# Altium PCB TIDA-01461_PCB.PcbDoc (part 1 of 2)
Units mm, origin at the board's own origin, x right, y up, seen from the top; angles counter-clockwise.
Board outline 92.5 x 57.5 mm, 4 copper layers (Top Layer, Mid Layer 1, Mid Layer 2, Bottom Layer), stack 1.54 mm thick; 150 components, 62 nets, 436 pads, 169 vias.
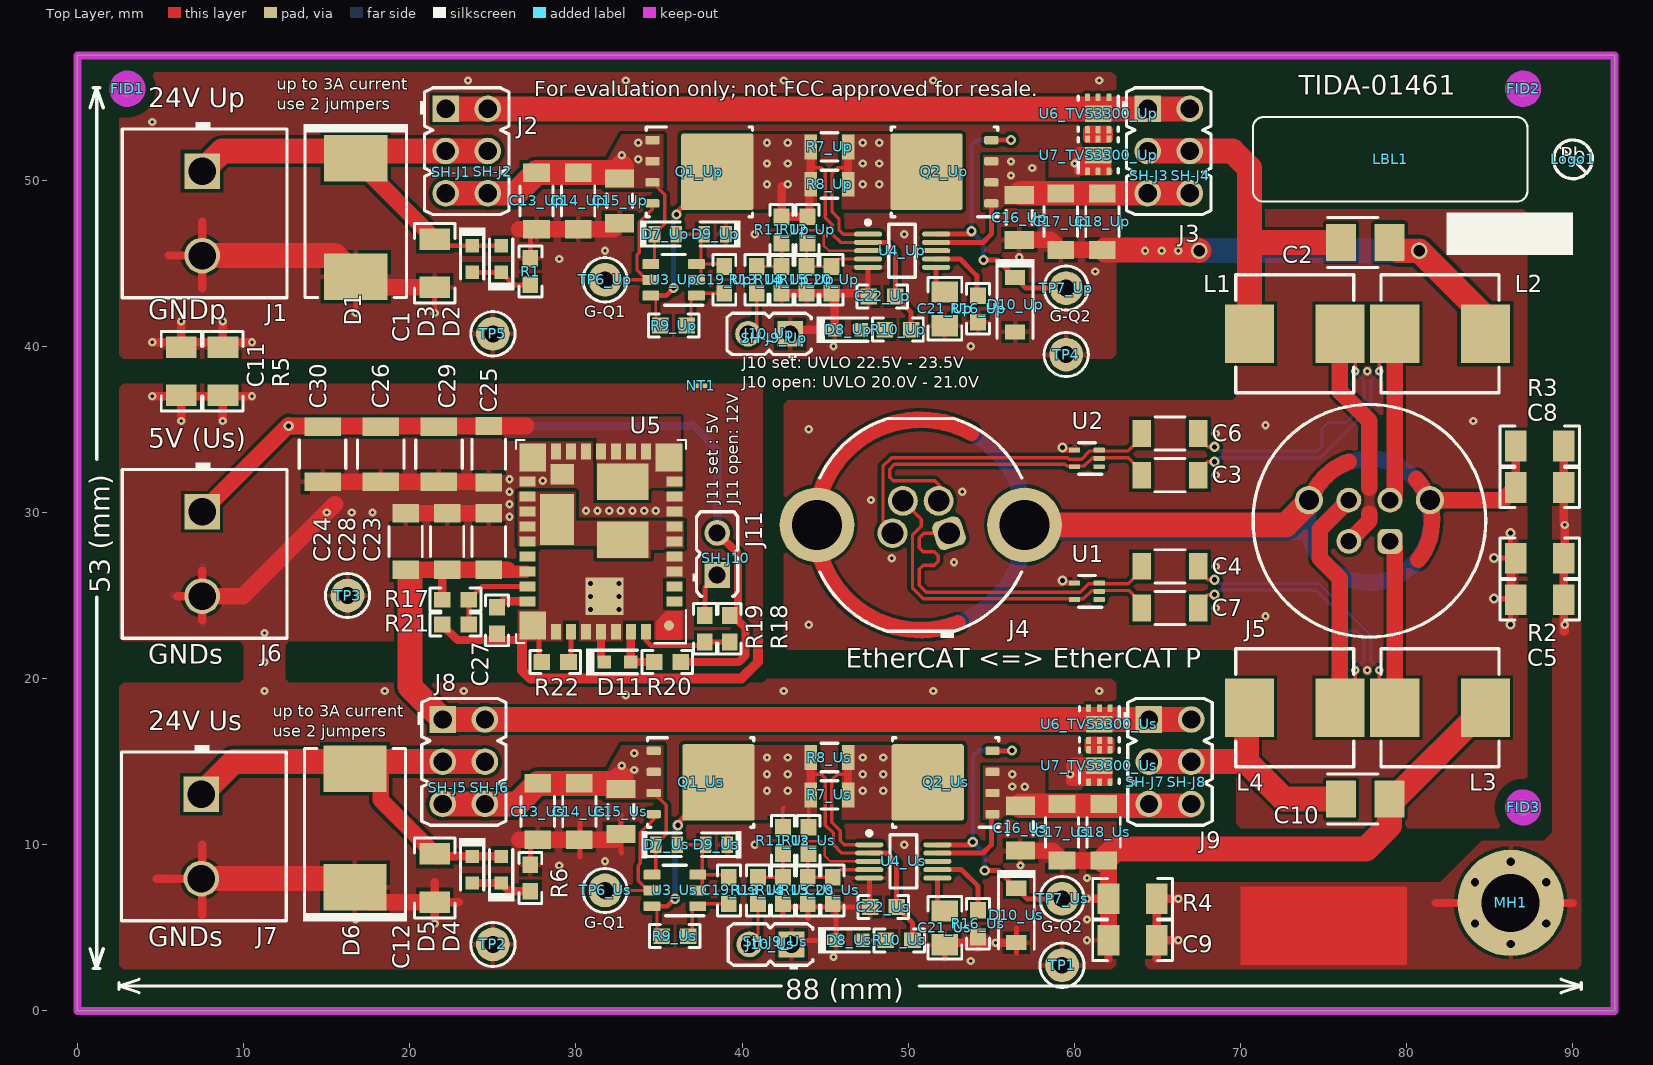
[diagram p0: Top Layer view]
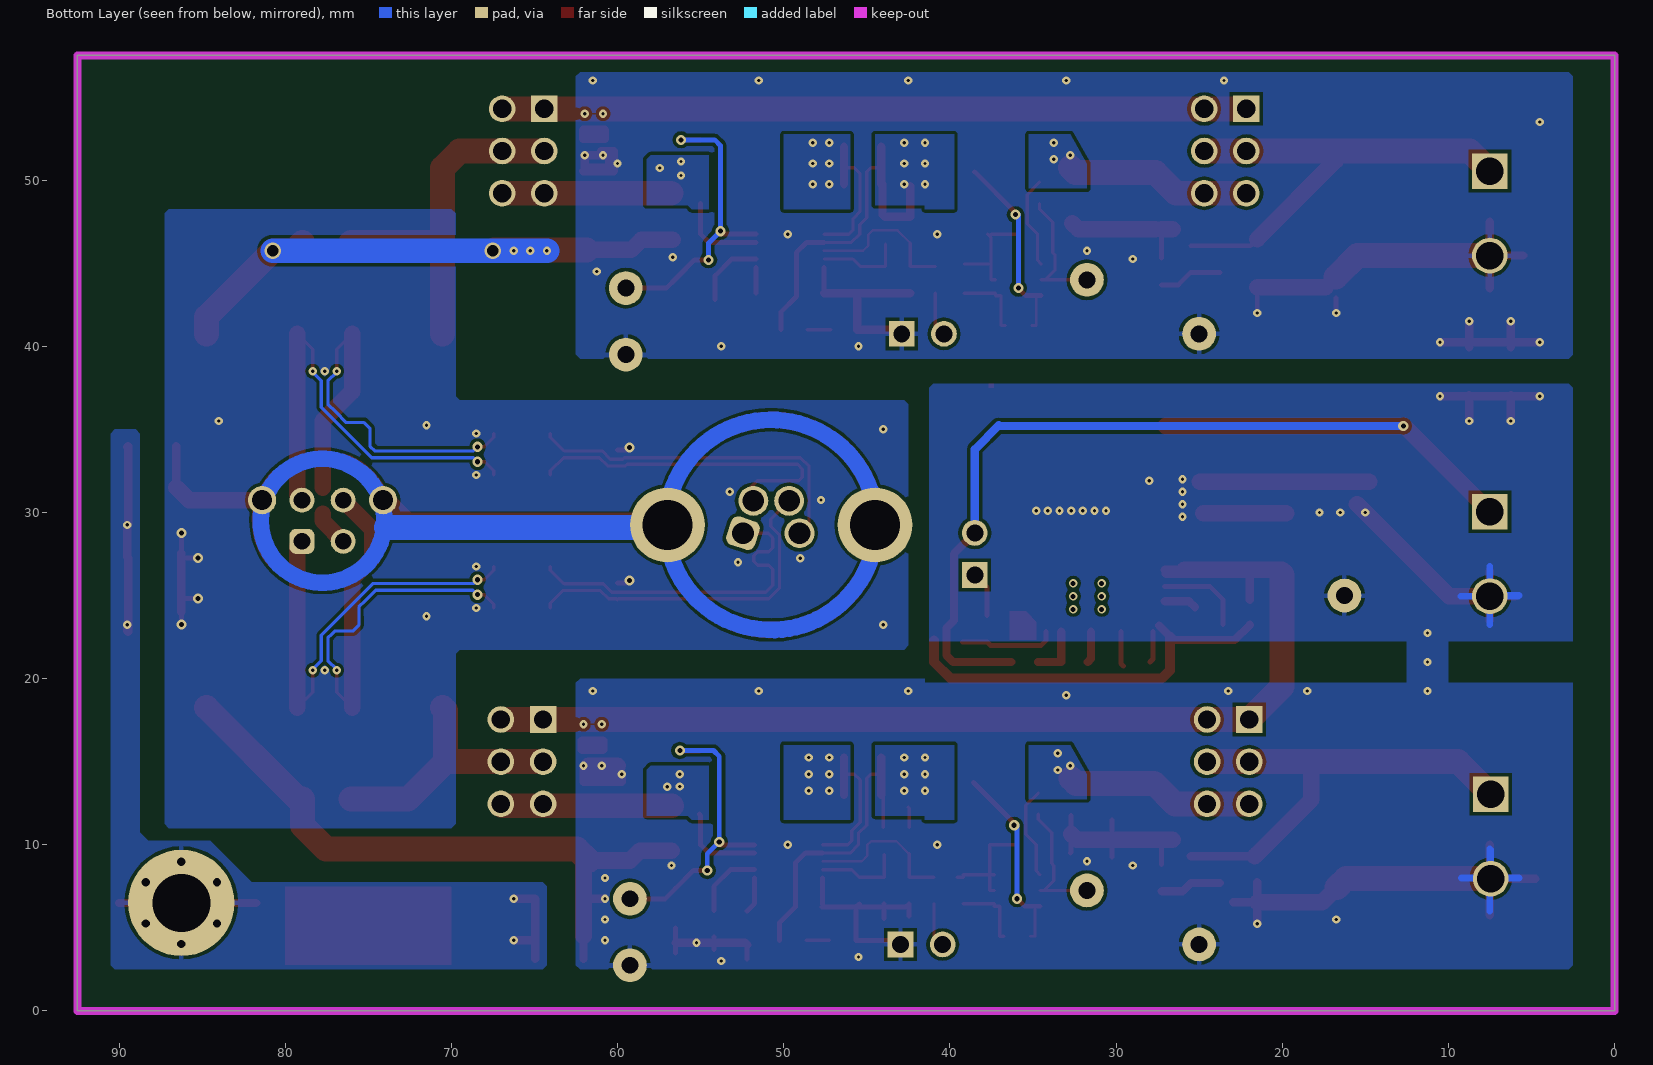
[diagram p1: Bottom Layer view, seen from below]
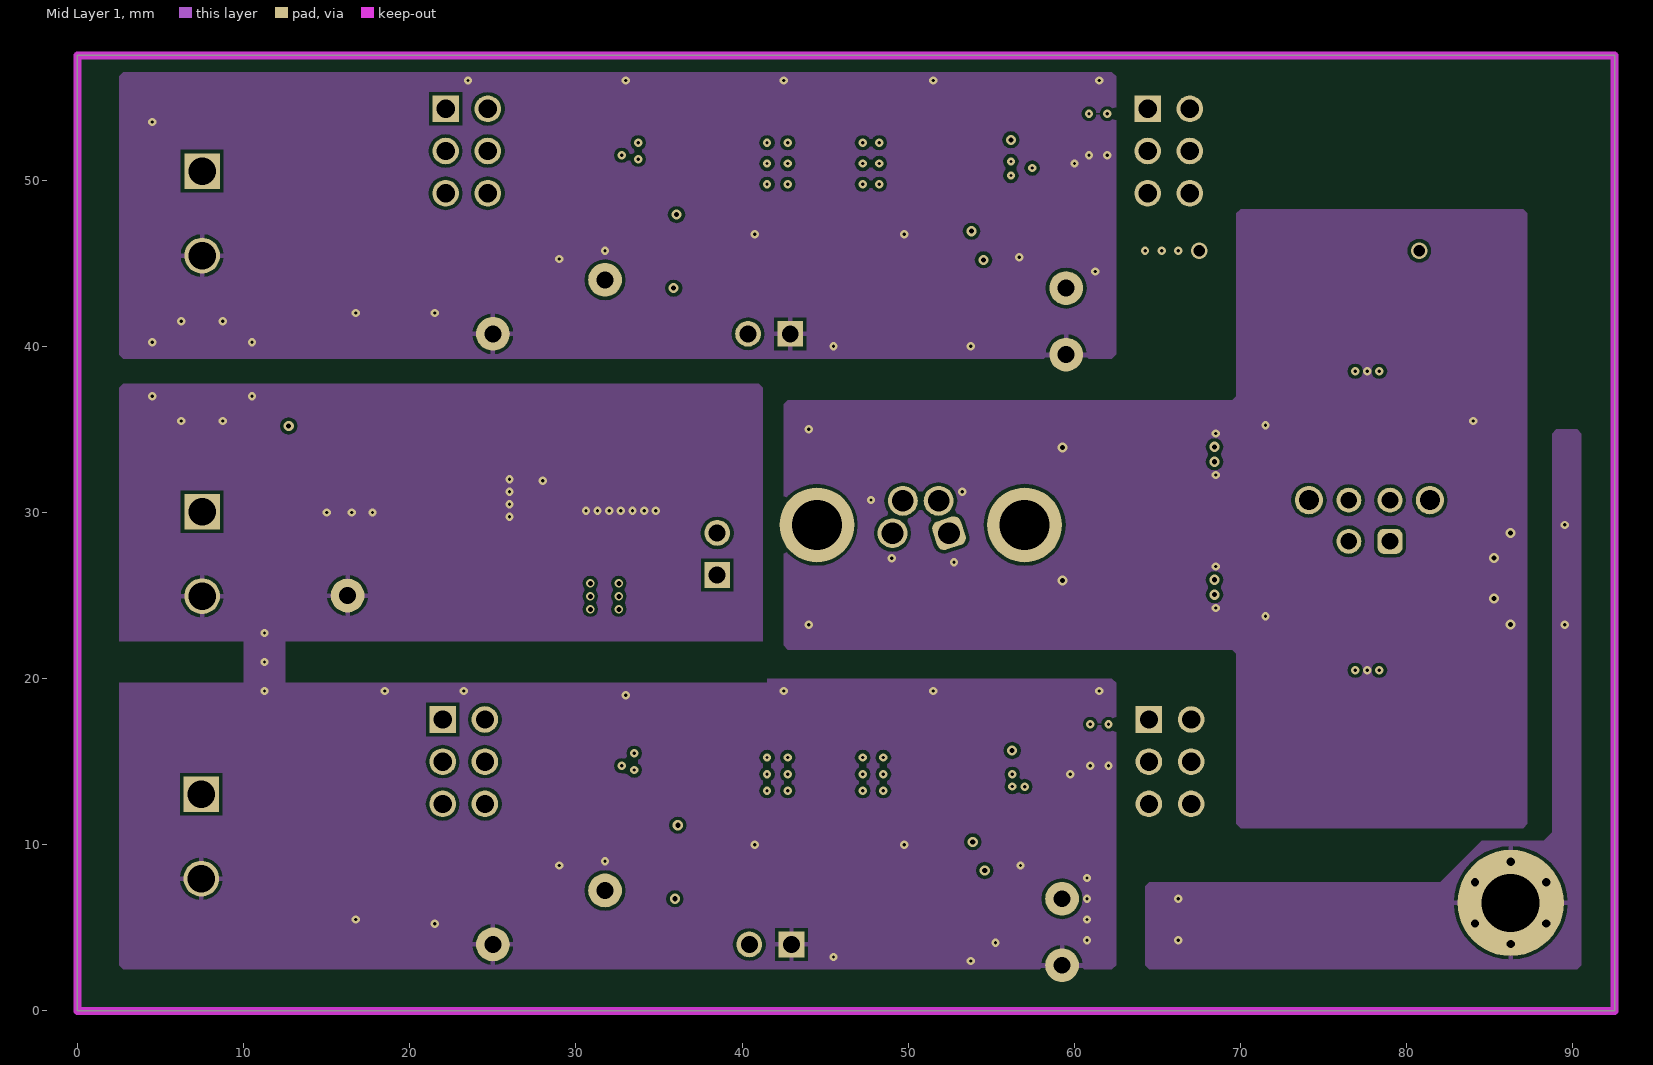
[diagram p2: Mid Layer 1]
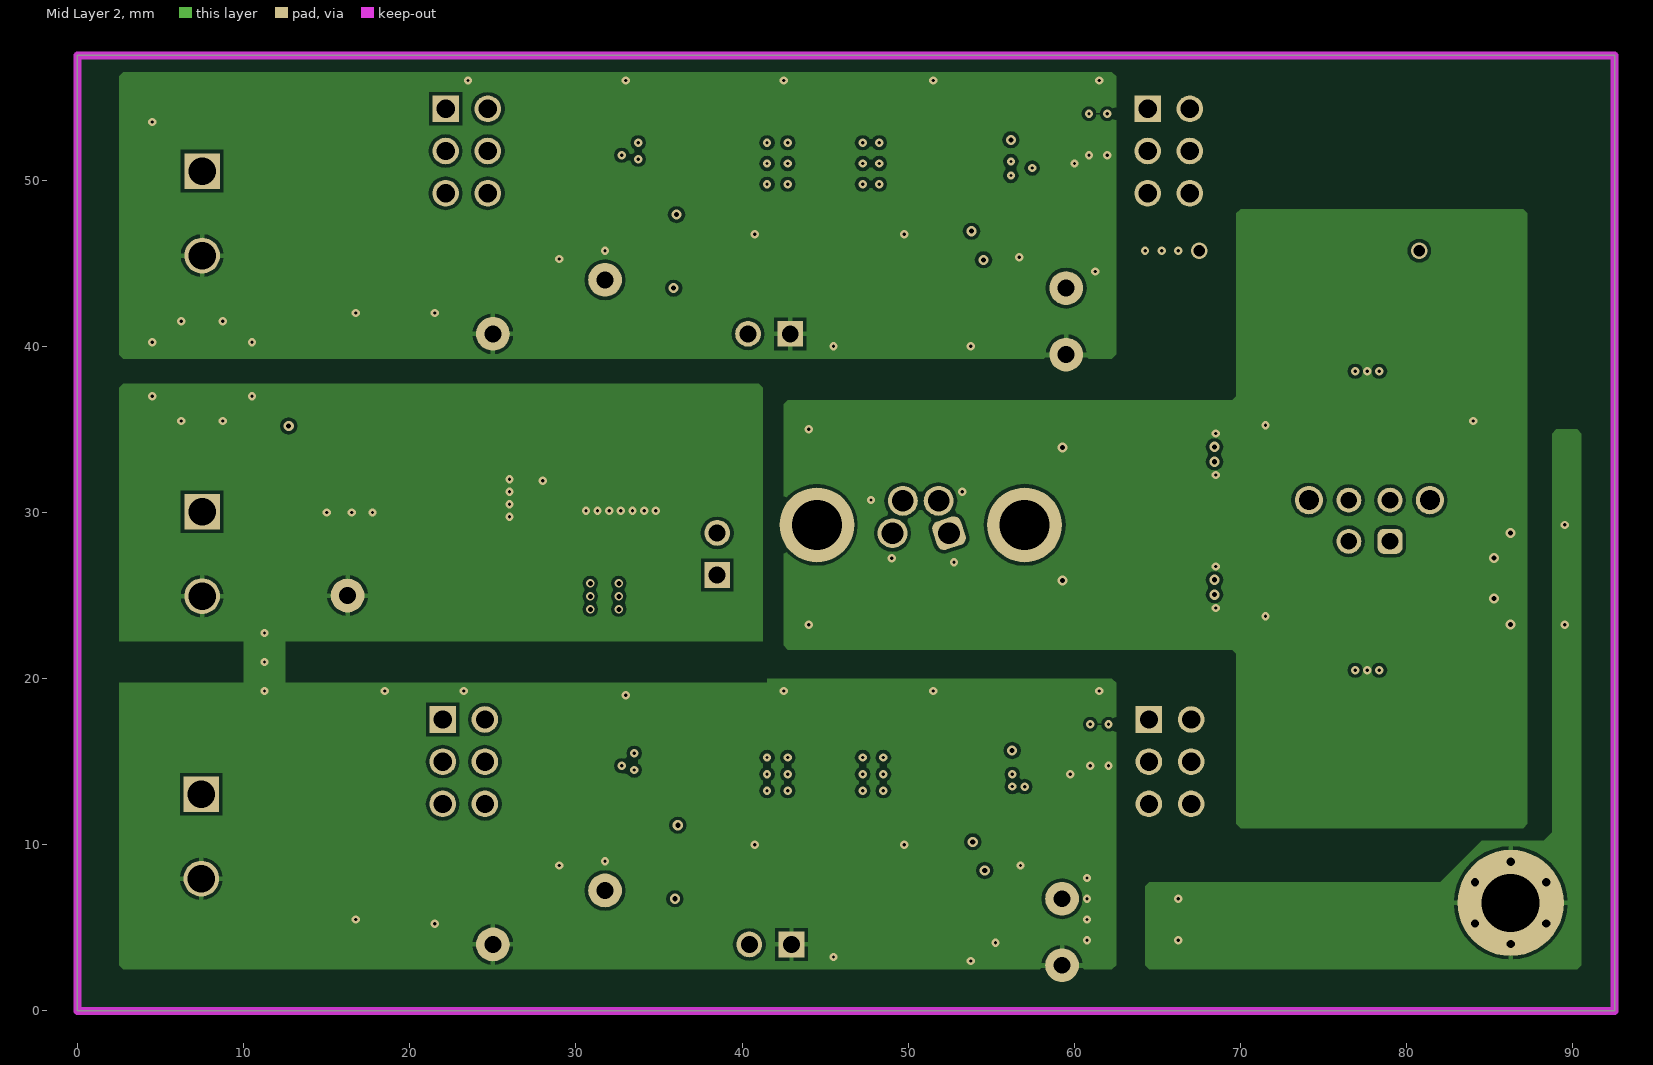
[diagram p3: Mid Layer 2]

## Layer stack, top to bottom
Top Solder: solder mask 0.015, Solder Resist, Dk 3.3
Top Layer: signal copper 0.035
Dielectric1: prepreg 0.2, FR-4, Dk 4.3
Mid Layer 1: signal copper 0.035
Dielectric 2: core 1, FR-4, Dk 4.6
Mid Layer 2: signal copper 0.035
Dielectric 3: prepreg 0.2, FR-4, Dk 4.3
Bottom Layer: signal copper 0.035
Bottom Solder: solder mask 0.015, Solder Resist, Dk 3.3

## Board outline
0,0 0,57.5 92.5,57.5 92.5,0

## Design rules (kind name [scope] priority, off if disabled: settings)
AcuteAngle [All] p1: minimum=4.50000000000000E+0001 checktracksonly=FALSE
AssemblyTestPointUsage [All] p1: valid=2
Clearance Clearance_FID [IsKeepOut and InComponentClass('FiducialMark') vs IsPad and InComponentClass('FiducialMark')] p1: gap=0 ignorepadtopadclearanceinfootprint=FALSE
Clearance Clearance_NetTie [InComponent('NT1')] p2: gap=0 ignorepadtopadclearanceinfootprint=TRUE
Clearance Clearance_PolysAGND-GND [InNamedPolygon('TOP_LAYER_GND_P243') vs InNamedPolygon('TOP_LAYER_AGND_P244')] p3: gap=0 ignorepadtopadclearanceinfootprint=FALSE
Clearance Clearance_MH [InComponent('MH1')] p4: gap=0.2 ignorepadtopadclearanceinfootprint=FALSE except(0: THPad-Via THPad-Hole)
Clearance Clearance_Keepouts [((IsTrack Or IsArc) And Not InPoly) And IsFree and IsKeepOut vs ((IsTrack Or IsArc) And Not InPoly) And IsFree and IsKeepOut] p5: gap=0 ignorepadtopadclearanceinfootprint=FALSE
Clearance Clearance_BoardEdge_MountingHoles [OnCopper and InComponentClass('Mounting Holes') vs IsKeepOut] p6: gap=1.016 ignorepadtopadclearanceinfootprint=FALSE except(0: Arc-Hole Track-Hole SMDPad-Hole THPad-Hole Via-Hole Fill-Hole Poly-Hole Region-Hole Text-Hole)
Clearance Clearance_BoardEdge_Poly [OnCopper and InPoly vs IsKeepOut] p7: gap=0.635 ignorepadtopadclearanceinfootprint=FALSE except(0: Arc-Hole Track-Hole SMDPad-Hole THPad-Hole Via-Hole Fill-Hole Poly-Hole Region-Hole Text-Hole)
Clearance Clearance_BoardEdge [OnCopper and Not InComponentClass('Logo') and not InComponentClass('FiducialMark') and not InRegion(1000,500,4000,800) and Not IsKeepout vs IsKeepOut] p8: gap=0.635 ignorepadtopadclearanceinfootprint=FALSE except(0: Arc-Hole Track-Hole SMDPad-Hole THPad-Hole Via-Hole Fill-Hole Poly-Hole Region-Hole Text-Hole)
Clearance Clearance_Poly [InPolygon] p9: gap=0.2 ignorepadtopadclearanceinfootprint=FALSE except(0: Arc-Hole Track-Hole SMDPad-Hole THPad-Hole Via-Hole Fill-Hole Poly-Hole Region-Hole Text-Hole)
Clearance [All] p10: gap=0.2 ignorepadtopadclearanceinfootprint=FALSE
ComponentClearance ComponentClearance_THtoTH_1 [HasFootprint('Major_BBB_SSHQ-123-D-08') vs HasFootprint('MTGP_4-40_PanHead')] p1: gap=0 collisioncheckmode=3 verticalgap=0 showdistances=FALSE
ComponentClearance ComponentClearance_MountingHoles_FiducialMarks [InComponentClass('Mounting Holes') vs InComponentClass('FiducialMark')] p2: gap=1.27 collisioncheckmode=3 verticalgap=0.254 showdistances=FALSE
ComponentClearance ComponentClearance_Shunt [InComponentClass('Header') vs InComponentClass('Shunt')] p3: gap=0 collisioncheckmode=3 verticalgap=0 showdistances=FALSE
ComponentClearance ComponentClearance_Logo [InComponentClass('Logo')] p4: gap=1.27 collisioncheckmode=3 verticalgap=0.254 showdistances=FALSE
ComponentClearance ComponentClearance_ScrewToNut [(HasFootprint('NY PMS 440 0025 PH')) vs (HasFootprint('Keystone_1902C'))] p5: gap=0.127 collisioncheckmode=3 verticalgap=0.254 showdistances=FALSE
ComponentClearance ComponentClearance_MountingHoles [InComponentClass('Mounting Holes')] p6: gap=6.35 collisioncheckmode=3 verticalgap=2540 showdistances=FALSE
ComponentClearance ComponentClearance_SmallPassives [HasFootprint('0201*') or HasFootprint('0402*') or HasFootprint('0508') or HasFootprint('0603*') or HasFootprint('0612') or HasFootprint('0805*') or HasFootprint('0815*') or HasFootprint('0830*') or HasFootprint('1206*') or HasFootprint('1210*') or HasFootprint('1808*') or HasFootprint('1812*') or HasFootprint('1825*') or HasFootprint('2010*') or HasFootprint('2220*') or HasFootprint('2225*') or HasFootprint('2512*') or HasFootprint('2728*') or HasFootprint('3518*') vs HasFootprint('0201*') or HasFootprint('0402*') or HasFootprint('0508') or HasFootprint('0603*') or HasFootprint('0612') or HasFootprint('0805*') or HasFootprint('0815*') or HasFootprint('0830*') or HasFootprint('1206*') or HasFootprint('1210*') or HasFootprint('1808*') or HasFootprint('1812*') or HasFootprint('1825*') or HasFootprint('2010*') or HasFootprint('2220*') or HasFootprint('2225*') or HasFootprint('2512*') or HasFootprint('2728*') or HasFootprint('3518*')] p7: gap=0.508 collisioncheckmode=3 verticalgap=0.254 showdistances=FALSE
ComponentClearance ComponentClearance_THtoSMT [IsThruComponent vs IsSMTComponent] p8: gap=0.508 collisioncheckmode=3 verticalgap=0.762 showdistances=FALSE
ComponentClearance ComponentClearance_THtoTH [IsThruComponent vs IsThruComponent] p9: gap=1.27 collisioncheckmode=3 verticalgap=0.508 showdistances=FALSE
DiffPairsRouting [All] p1: maxlimit=2 minlimit=0.2 mostfreqgap=0.2 toplayer_minwidth=0.2 toplayer_maxwidth=1 toplayer_prefwidth=0.2 midlayer1_minwidth=0.2 midlayer1_maxwidth=1 midlayer1_prefwidth=0.2 midlayer2_minwidth=0.2 midlayer2_maxwidth=1 midlayer2_prefwidth=0.2 bottomlayer_minwidth=0.2 bottomlayer_maxwidth=1 bottomlayer_prefwidth=0.2 maxuncoupledlength=25.4
FabricationTestPointUsage TestPointUsage [All] p1: valid=2 allowmultiple=FALSE
FabricationTestpoint Testpoint [All] p1: side=3 testpointundercomponent=TRUE minsize=1.016 maxsize=2.54 preferedsize=1.524 minholesize=0 maxholesize=1.016 preferedholesize=0.813 testpointgrid=0.025 allowsidetop=TRUE allowsidebottom=TRUE usegrid=TRUE gridtolerance=0
FanoutControl Fanout_LCC [IsLCC] p1: bgadir=Out bgaviamode=Centered fanoutstyle=Auto fanoutdirection=Alternating viagrid=0.025 // Fanout_LCC (Default Rule)
FanoutControl Fanout_BGA [IsBGA] p2: bgadir=Out bgaviamode=Centered fanoutstyle=Auto fanoutdirection=Alternating viagrid=0.025 // Fanout_BGA (Default Rule)
FanoutControl Fanout_Default [All] p4: bgadir=Out bgaviamode=Centered fanoutstyle=Auto fanoutdirection=Alternating viagrid=0.025 // Fanout_Default (Default Rule)
FanoutControl Fanout_Small [(CompPinCount < 5)] p5: bgadir=Out bgaviamode=Centered fanoutstyle=Auto fanoutdirection=OutThenIn viagrid=0.025 // Fanout_Small (Default Rule)
Height [All] p1: minheight=0 maxheight=26 prefheight=12.7
HoleSize [All] p1: absolutevalues=TRUE maxlimit=6.375 minlimit=0.2 maxpercent=80.000 minpercent=20.000
HoleToHoleClearance [All] p1: gap=0.2 allowstackedmicrovias=TRUE
MinimumAnnularRing MinimumAnnularRing_LMZ [InComponent('U5')] p1: minimumring=0.1
MinimumAnnularRing MinimumAnnularRing_ThermalPadVias [IsVia and InAnyComponent] p2: minimumring=0.15
MinimumAnnularRing [All] p3: minimumring=0.15
MinimumSolderMaskSliver MinimumSolderMaskSliver_Logo [InComponentClass('Logo') vs InComponentClass('Logo')] p1: minsoldermaskwidth=0.015
MinimumSolderMaskSliver [All] p2: minsoldermaskwidth=0.1
PlaneConnect [All] p1: planeconnectstyle=Direct reliefexpansion=0.254 reliefentries=4 reliefconductorwidth=0.254 reliefairgap=0.254
PolygonConnect PolygonConnect_1 [All vs IsNamedPolygon('TOP_LAYER_NETC22_US_1_P235') Or  IsNamedPolygon('TOP_LAYER_NETQ2_US_5_P236') Or  IsNamedPolygon('TOP_LAYER_PWR_IN_US_P234') Or  IsNamedPolygon('BOTTOM_LAYER_NETQ2_UP_5_P252') Or  IsNamedPolygon('TOP_LAYER_GND_P243') Or  IsNamedPolygon('BOTTOM_LAYER_UP_PROTECTED_P253') Or  IsNamedPolygon('TOP_LAYER_US_PROTECTED_P237') Or  IsNamedPolygon('TOP_LAYER_NETQ2_UP_5_P240') Or  IsNamedPolygon('TOP_LAYER_AGND_P244') Or  IsNamedPolygon('TOP_LAYER_BUCK_OUT_P245') Or  IsNamedPolygon('BOTTOM_LAYER_NETC22_US_1_P248') Or  IsNamedPolygon('BOTTOM_LAYER_US_PROTECTED_P246') Or  IsNamedPolygon('BOTTOM_LAYER_PWR_IN_UP_P250') Or  IsNamedPolygon('TOP_LAYER_PWR_IN_UP_P238') Or  IsNamedPolygon('BOTTOM_LAYER_NETQ2_US_5_P247') Or  IsNamedPolygon('TOP_LAYER_NETC22_UP_1_P239') Or  IsNamedPolygon('BOTTOM_LAYER_NETC22_UP_1_P251') Or  IsNamedPolygon('BOTTOM_LAYER_PWR_IN_US_P249') Or  IsNamedPolygon('TOP_LAYER_PH_P241') Or  IsNamedPolygon('TOP_LAYER_UP_PROTECTED_P242')] p1: connectstyle=Direct reliefconductorwidth=0.254 reliefentries=4 polygonreliefangle="90 Angle" airgapwidth=0.254
PolygonConnect [All] p2: thpad.connectstyle=Relief thpad.reliefconductorwidth=0.3 thpad.reliefentries=4 thpad.polygonreliefangle="90 Angle" thpad.airgapwidth=0.2 smdpad.connectstyle=Relief smdpad.reliefconductorwidth=0.3 smdpad.reliefentries=4 smdpad.polygonreliefangle="90 Angle" smdpad.airgapwidth=0.2 via.connectstyle=Direct via.reliefconductorwidth=0.3 via.reliefentries=4 via.polygonreliefangle="90 Angle" via.airgapwidth=0.2
RoutingVias RoutingVias_FID [IsVia and Component = 'FID*'] p1: holewidth=0.711 width=1.27 viastyle="Through Hole" minholewidth=0 minwidth=0 maxholewidth=0.711 maxwidth=1.27
RoutingVias ThermalPadVias [IsVia and InAnyComponent] p2: holewidth=0.2 width=0.5 viastyle="Through Hole" minholewidth=0.2 minwidth=0.5 maxholewidth=1 maxwidth=1.3
RoutingVias [All] p3: holewidth=0.2 width=0.5 viastyle="Through Hole" minholewidth=0.2 minwidth=0.5 maxholewidth=1 maxwidth=1.3
ShortCircuit ShortCircuit_NetTie [Component = 'NT1'] p1: allowed=TRUE
ShortCircuit ShortCircuit_PolysAGND-GND [InNamedPolygon('TOP_LAYER_AGND_P244') vs InNamedPolygon('TOP_LAYER_GND_P243')] p2: allowed=TRUE
ShortCircuit ShortCircuit_MH [InPadClass('MHclass')] p3: allowed=TRUE
ShortCircuit [All] p4: allowed=FALSE
SilkToBoardRegionClearance [Not ((IsComment or IsDesignator) And (Hide <> 'False')) and not InRegion(1000,500,4000,800)] p1:
SilkToSilkClearance SilkToSilkClearance_Pb-FreeLogo [(HasFootprint('Pb-Free_Overlay_Medium') OR HasFootprint('Pb-Free_Overlay_Small')) vs (HasFootprint('Pb-Free_Overlay_Medium') OR HasFootprint('Pb-Free_Overlay_Small'))] p1 off: silktosilkclearance=0
SilkToSilkClearance [All] p2 off: silktosilkclearance=0.127
SilkToSolderMaskClearance "Silk to Solder Mask Opening" [All] p1 off: minsilkscreentomaskgap=0.025 clearancetoexposedcopper=FALSE
SolderMaskExpansion SolderMaskExpansion_Via [IsVia] p1: expansion=0.1 soldermaskfromhole=TRUE
SolderMaskExpansion [All AND NOT IsVIA] p2: expansion=0.05
Width [All] p1: maxlimit=2 minlimit=0.15 preferedwidth=0.2 checkconnectedcopper=TRUE
12 further rules are at their usual default settings.

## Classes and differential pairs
channel class TIDA-01461_TVS3300: TVS3300_Up TVS3300_Us
component class U_TIDA-01461_Hardware: !PCB1 FID1 FID2 FID3 LBL1 Logo1 Logo2 ZZ1 ZZ2 ZZ3 ZZ4
component class Buck: C23 C24 C25 C26 C27 C28 C29 C30 D11 J11 NT1 R17 R18 R19 R20 R21 R22 SH-J10 U5
component class Label: LBL1
component class FiducialMark: FID1 FID2 FID3
component class AssemblyNote: ZZ1 ZZ2 ZZ3 ZZ4
component class U_TIDA-01461_PowerStage: C1 C2 C3 C4 C5 C6 C7 C8 C9 C10 C11 C12 D1 D2 D3 D4 D5 D6 D7 J1 J2 J3 J4 J5 J6 J7 J8 J9 L1 L2 L3 L4 MH1 R1 R2 R3 R4 R5 R6 SH-J1 SH-J2 SH-J3 SH-J4 SH-J5 SH-J6 SH-J7 SH-J8 TP1 TP2 TP3 TP4 TP5 U1 U2
component class Header: J2 J3 J8 J9 J10_Up J10_Us J11
component class Up: C13_Up C14_Up C15_Up C16_Up C17_Up C18_Up C19_Up C20_Up C21_Up C22_Up D7_Up D8_Up D9_Up D10_Up J10_Up Q1_Up Q2_Up R7_Up R8_Up R9_Up R10_Up R11_Up R12_Up R13_Up R14_Up R15_Up R16_Up SH-J9_Up TP6_Up TP7_Up U3_Up U4_Up
component class Us: C13_Us C14_Us C15_Us C16_Us C17_Us C18_Us C19_Us C20_Us C21_Us C22_Us D7_Us D8_Us D9_Us D10_Us J10_Us Q1_Us Q2_Us R5_Us R7_Us R8_Us R9_Us R10_Us R11_Us R12_Us R13_Us R14_Us R15_Us R16_Us SH-J9_Us TP6_Us TP7_Us U3_Us U4_Us
channel class TIDA-01461_PowerInputProtection: Up Us
component class TVS3300_Up: U6_TVS3300_Up U7_TVS3300_Up
component class TVS3300_Us: U6_TVS3300_Us U7_TVS3300_Us
polygon class PolygonClass_1: TOP_LAYER_RXEP_N_P112
pad class MHclass: MH1-1
component class Shunt: SH-J1 SH-J2 SH-J3 SH-J4 SH-J5 SH-J6 SH-J7 SH-J8 SH-J9_Up SH-J9_Us SH-J10
differential pair RXEP: +RXEP_P -RXEP_N
differential pair RXE: +RXE_P -RXE_N
differential pair TXEP: +TXEP_P -TXEP_N
differential pair TXE: +TXE_P -TXE_N

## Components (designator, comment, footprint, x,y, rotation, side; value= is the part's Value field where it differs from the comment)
C1 "GRM319R72A104KA01D" 1206 21.5,45 r90 top value=0.1uF
C2 "TCJB106M035R0200" 3528-21 77.5,46.25 r0 top value=10uF
C3 "GRM31CR72A105KA01L" 1206_180 65.75,32.25 r180 top value=1uF
C4 "GRM31CR72A105KA01L" 1206_180 65.75,26.75 r180 top value=1uF
C5 "VJ1206Y103KXEAT5Z" 1206 88,24.75 r180 top value=0.01uF
C6 "GRM31CR72A105KA01L" 1206_180 65.75,34.75 r180 top value=1uF
C7 "GRM31CR72A105KA01L" 1206_180 65.75,24.25 r180 top value=1uF
C8 "VJ1206Y103KXEAT5Z" 1206 88,31.5 r180 top value=0.01uF
C9 "VJ1206Y103KXEAT5Z" 1206 63.5,4.25 r180 top value=0.01uF
C10 "TCJB106M035R0200" 3528-21 77.5,12.75 r0 top value=10uF
C11 "VJ1206Y103KXEAT5Z" 1206 6.25,38.5 r270 top value=0.01uF
C12 "GRM319R72A104KA01D" 1206 21.5,8 r270 top value=0.1uF
C13_Up "GRM31CR71H475KA12L" 1206_180 27.625,48.75 r270 top value=4.7uF (schematic designator C13)
C13_Us "GRM31CR71H475KA12L" 1206_180 27.7,12 r270 top value=4.7uF (schematic designator C13)
C14_Up "GRM31CR72A105KA01L" 1206_180 30.125,48.75 r270 top value=1uF (schematic designator C14)
C14_Us "GRM31CR72A105KA01L" 1206_180 30.2,12 r270 top value=1uF (schematic designator C14)
C15_Up "GRM319R72A104KA01D" 1206L 32.625,48.75 r270 top value=0.1uF (schematic designator C15)
C15_Us "GRM319R72A104KA01D" 1206L 32.7,12 r270 top value=0.1uF (schematic designator C15)
C16_Up "GRM319R72A104KA01D" 1206L 56.675,47.75 r270 top value=0.1uF (schematic designator C16)
C16_Us "GRM319R72A104KA01D" 1206L 56.75,11 r270 top value=0.1uF (schematic designator C16)
C17_Up "GRM31CR72A105KA01L" 1206_180 59.175,47.5 r270 top value=1uF (schematic designator C17)
C17_Us "GRM31CR72A105KA01L" 1206_180 59.25,10.75 r270 top value=1uF (schematic designator C17)
C18_Up "GRM31CR71H475KA12L" 1206_180 61.675,47.5 r270 top value=4.7uF (schematic designator C18)
C18_Us "GRM31CR71H475KA12L" 1206_180 61.75,10.75 r270 top value=4.7uF (schematic designator C18)
C19_Up "GRM188R72A104KA35D" 0603 38.925,44 r90 top value=0.1uF (schematic designator C19)
C19_Us "GRM188R72A104KA35D" 0603 39.2,7.25 r90 top value=0.1uF (schematic designator C19)
C20_Up "GRM188R61H102KA01D" 0603 45.375,44 r270 top value=1000pF (schematic designator C20)
C20_Us "GRM188R61H102KA01D" 0603 45.45,7.25 r270 top value=1000pF (schematic designator C20)
C21_Up "GRM21BR71C335KA99L" 0805_HV 52.2,42.25 r270 top value=3.3uF (schematic designator C21)
C21_Us "GRM21BR71C335KA99L" 0805_HV 52.2,5 r270 top value=3.3uF (schematic designator C21)
C22_Up "06035C104KAT2A" 0603 48.425,43 r180 top value=0.1uF (schematic designator C22)
C22_Us "06035C104KAT2A" 0603 48.5,6.25 r180 top value=0.1uF (schematic designator C22)
C23 "GRM31CR71H475KA12L" 1206_180 24.75,28.25 r90 top value=4.7uF
C24 "GRM31CR72A105KA01L" 1206_180 19.75,28.25 r270 top value=1uF
C25 "GRM31CR71H475KA12L" 1206_180 24.75,33.5 r270 top value=4.7uF
C26 "12103D226MAT2A" 1210_280 18.25,33.5 r270 top value=22uF
C27 "GRM188R71H223KA01D" 0603 25.25,23.5 r270 top value=0.022uF
C28 "GRM31CR71H475KA12L" 1206_180 22.25,28.25 r90 top value=4.7uF
C29 "12103D226MAT2A" 1210_280 21.75,33.5 r270 top value=22uF
C30 "12103D226MAT2A" 1210_280 14.75,33.5 r270 top value=22uF
D1 "SMCJ33CA" SMC 16.75,47.75 r270 top value=33V
D2 "150060GS75000" WL-SMCW_GREEN 25.5,45.25 r90 top value=Green
D3 "150060RS75000" WL-SMCW_RED 23.75,45.25 r270 top value=Red
D4 "150060GS75000" WL-SMCW_GREEN 25.5,8.5 r90 top value=Green
D5 "150060RS75000" WL-SMCW_RED 23.75,8.5 r270 top value=Red
D6 "SMCJ33CA" SMC 16.7,11 r90 top value=33V
D7_Up "CD0603-S01575" Diode_0603 35.375,46.75 r0 top value=100V (schematic designator D7)
D7_Us "CD0603-S01575" Diode_0603 35.45,10 r0 top value=100V (schematic designator D7)
D8_Up "150060BS75000" WL-SMCW_Blue 46.375,41 r0 top value=Blue (schematic designator D8)
D8_Us "150060BS75000" WL-SMCW_Blue 46.45,4.25 r0 top value=Blue (schematic designator D8)
D9_Up "CD0603-S01575" Diode_0603 38.375,46.75 r180 top value=100V (schematic designator D9)
D9_Us "CD0603-S01575" Diode_0603 38.45,10 r180 top value=100V (schematic designator D9)
D10_Up "BZT52C33-7-F" SOD-123 56.425,42.5 r270 top value=33V (schematic designator D10)
D10_Us "BZT52C33-7-F" SOD-123 56.5,5.75 r270 top value=33V (schematic designator D10)
D11 "150060GS75000" WL-SMCW_GREEN 32.5,21 r0 top value=Green
FID1 "Fiducial" Fiducial10-20 3,55.5 r0 top
FID2 "Fiducial" Fiducial10-20 87,55.5 r0 top
FID3 "Fiducial" Fiducial10-20 87,12.25 r0 top
J1 "039544-3002" Molex_039544-3002 7.5,48 r270 top
J2 "61300621121" Wurth_61300621121 23.425,51.75 r0 top
J3 "61300621121" Wurth_61300621121 65.675,51.75 r0 top
J4 "09 3420 81 04" Binder_09_3420_81_04 50.75,29.25 r180 top locked
J5 "ZS7002-0001" Beckhoff_ZS7002-0001 77.75,29.5 r0 top
J6 "039544-3002" Molex_039544-3002 7.5,27.5 r270 top
J7 "039544-3002" Molex_039544-3002 7.45,10.5 r270 top
J8 "61300621121" Wurth_61300621121 23.25,15 r0 top
J9 "61300621121" Wurth_61300621121 65.75,15 r0 top
J10_Up "0022284023" Molex_0022284023 41.625,40.75 r180 top (schematic designator J10)
J10_Us "0022284023" Molex_0022284023 41.7,4 r180 top (schematic designator J10)
J11 "0022284023" Molex_0022284023 38.5,27.5 r90 top
L1 "74437346068" WE-LHMI_7030 73.25,40.75 r0 top value=6.8uH
L2 "74437346068" WE-LHMI_7030 82,40.75 r180 top value=6.8uH
L3 "74437346068" WE-LHMI_7030 82,18.25 r180 top value=6.8uH
L4 "74437346068" WE-LHMI_7030 73.25,18.25 r0 top value=6.8uH
LBL1 "Size: 0.65\" x 0.20 \"" Label_650x200 79,51.25 r0 top
Logo1 "Pb-Free Symbol" Pb-Free_Overlay_Small 90,51.25 r0 top
Logo2 "FCC disclaimer" FCC_disclaimer 89.175,68 r0 top
MH1 "MTG_Pads" MTGP_4-40_PanHead 86.25,6.5 r0 top
NT1 "Net-Tie" Net-Tie_10mil 37.5,37.625 r180 top net-tie
Q1_Up "CSD18540Q5B" DNK0008A 37.425,50.5 r0 top value=60V (schematic designator Q1)
Q1_Us "CSD18540Q5B" DNK0008A 37.5,13.75 r0 top value=60V (schematic designator Q1)
Q2_Up "CSD18540Q5B" DNK0008A 52.175,50.5 r180 top value=60V (schematic designator Q2)
Q2_Us "CSD18540Q5B" DNK0008A 52.25,13.75 r180 top value=60V (schematic designator Q2)
R1 "CRCW060310K0FKEA" 0603 27.25,44.5 r270 top value=10.0k
R2 "CRCW12061M00FKEA" 1206 88,27.25 r0 top value=1.00Meg
R3 "CRCW12061M00FKEA" 1206 88,34 r0 top value=1.00Meg
R4 "CRCW12061M00FKEA" 1206 63.5,6.75 r0 top value=1.00Meg
R5 "CRCW12061M00FKEA" 1206 8.75,38.5 r90 top value=1.00Meg
R6 "CRCW060310K0FKEA" 0603 27.25,8 r90 top value=10.0k
R7_Up "KRL1220E-M-R018-F-T5" KRL1220 45.25,52 r0 top value=0.018 (schematic designator R7)
R7_Us "KRL1220E-M-R018-F-T5" KRL1220 45.25,13 r0 top value=0.018 (schematic designator R7)
R8_Up "KRL1220E-M-R018-F-T5" KRL1220 45.25,49.75 r0 top value=0.018 (schematic designator R8)
R8_Us "KRL1220E-M-R018-F-T5" KRL1220 45.25,15.25 r0 top value=0.018 (schematic designator R8)
R9_Up "RC0603FR-07100RL" 0603 35.875,41.25 r180 top value=100 (schematic designator R9)
R9_Us "RC0603FR-07100RL" 0603 35.95,4.5 r180 top value=100 (schematic designator R9)
R10_Up "CRCW060310K0FKEA" 0603 49.375,41 r0 top value=10.0k (schematic designator R10)
R10_Us "CRCW060310K0FKEA" 0603 49.45,4.25 r0 top value=10.0k (schematic designator R10)
R11_Up "RC0603FR-0747KL" 0603 42.375,47 r90 top value=47.0k (schematic designator R11)
R11_Us "RC0603FR-0747KL" 0603 42.45,10.25 r90 top value=47.0k (schematic designator R11)
R12_Up "RC0603FR-0747KL" 0603 43.925,47 r90 top value=47.0k (schematic designator R12)
R12_Us "RC0603FR-0747KL" 0603 44,10.25 r90 top value=47.0k (schematic designator R12)
R13_Up "RC0603FR-07115KL" 0603 40.875,44 r90 top value=115k (schematic designator R13)
R13_Us "RC0603FR-07115KL" 0603 40.95,7.25 r90 top value=115k (schematic designator R13)
R14_Up "RC0603FR-076K2L" 0603 42.375,44 r90 top value=6.20k (schematic designator R14)
R14_Us "RC0603FR-076K2L" 0603 42.45,7.25 r90 top value=6.20k (schematic designator R14)
R15_Up "RC0603FR-074K42L" 0603 43.875,44 r90 top value=4.42k (schematic designator R15)
R15_Us "RC0603FR-074K42L" 0603 43.95,7.25 r90 top value=4.42k (schematic designator R15)
R16_Up "CRCW060314K0FKEA" 0603 54.2,42.25 r90 top value=14.0k (schematic designator R16)
R16_Us "CRCW060314K0FKEA" 0603 54.2,5.25 r90 top value=14.0k (schematic designator R16)
R17 "CRCW0603174KFKEA" 0603 22.75,24.75 r180 top value=174k
R18 "CRCW0603140KFKEA" 0603 39.25,23 r270 top value=140k
R19 "CRCW060384K5FKEA" 0603 37.75,23 r270 top value=84.5k
R20 "CRCW06032K21FKEA" 0603 35.5,21 r0 top value=2.21k
R21 "CRCW060311K5FKEA" 0603 22.75,23.25 r0 top value=11.5k
R22 "CRCW0603267KFKEA" 0603 28.75,21 r0 top value=267k
SH-J1 "60900213421" Wurth_60900213421 22.5,50.475 r90 top
SH-J2 "60900213421" Wurth_60900213421 25,50.5 r90 top
SH-J3 "60900213421" Wurth_60900213421 64.5,50.25 r90 top
SH-J4 "60900213421" Wurth_60900213421 67,50.25 r90 top
SH-J5 "60900213421" Wurth_60900213421 22.28,13.418 r90 top
SH-J6 "60900213421" Wurth_60900213421 24.82,13.418 r90 top
SH-J7 "60900213421" Wurth_60900213421 64.25,13.75 r90 top
SH-J8 "60900213421" Wurth_60900213421 66.75,13.75 r90 top
SH-J9_Up "60900213421" Wurth_60900213421 41.92,40.495 r180 top (schematic designator SH-J9)
SH-J9_Us "60900213421" Wurth_60900213421 41.995,4.15 r0 top (schematic designator SH-J9)
SH-J10 "60900213421" Wurth_60900213421 39,27.25 r90 top
TP1 "5001" Keystone5001 59.25,2.75 r90 top
TP2 "5001" Keystone5001 25,4 r90 top
TP3 "5001" Keystone5001 16.25,25 r90 top
TP4 "5001" Keystone5001 59.5,39.5 r90 top
TP5 "5001" Keystone5001 25,40.75 r90 top
TP6_Up "5004" Keystone5004 31.75,44 r90 top (schematic designator TP6)
TP6_Us "5004" Keystone5004 31.75,7.25 r90 top (schematic designator TP6)
TP7_Up "5004" Keystone5004 59.5,43.5 r90 top (schematic designator TP7)
TP7_Us "5004" Keystone5004 59.25,6.75 r90 top (schematic designator TP7)
U1 "TPD2E2U06DRLR" DRL0005A 60.75,25.25 r180 top
U2 "TPD2E2U06DRLR" DRL0005A 60.75,33.25 r180 top
U3_Up "LM5050MK-1/NOPB" DDC0006A_N 35.875,44 r180 top (schematic designator U3)
U3_Us "LM5050MK-1/NOPB" DDC0006A_N 35.95,7.25 r180 top (schematic designator U3)
U4_Up "LM5069MM-2/NOPB" MUB10A_N 49.625,45.75 r0 top (schematic designator U4)
U4_Us "LM5069MM-2/NOPB" MUB10A_N 49.7,9 r0 top (schematic designator U4)
U5 "LMZ35003RKGR" RKG0041A 31.5,28.25 r180 top
U6_TVS3300_Up "TVS3300DRVR" DRV0006A 61.425,54 r270 top (schematic designator U6)
U6_TVS3300_Us "TVS3300DRVR" DRV0006A 61.5,17.25 r270 top (schematic designator U6)
U7_TVS3300_Up "TVS3300DRVR" DRV0006A 61.425,51.5 r90 top (schematic designator U7)
U7_TVS3300_Us "TVS3300DRVR" DRV0006A 61.5,14.75 r90 top (schematic designator U7)
ZZ1 "This Assembly Note is for PCB labels only" AssemblyNoteLabel 5,105.5 r0 top
ZZ2 "These assemblies are ESD sensitive, ESD precautions shall be observed." AssemblyNote 5,103 r0 top
ZZ3 "These assemblies must be clean and free from flux and all contaminants. Use of no clean flux is not acceptable." AssemblyNote 5,101.25 r0 top
ZZ4 "These assemblies must comply with workmanship standards IPC-A-610 Class 2, unless otherwise specified." AssemblyNote 5,99 r0 top

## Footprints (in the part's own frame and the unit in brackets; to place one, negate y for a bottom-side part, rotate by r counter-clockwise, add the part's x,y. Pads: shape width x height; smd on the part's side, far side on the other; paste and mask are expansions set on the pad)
0603 [mm] "0603 from SM-752 data"
  rect 1x0.95 smd: 1(-0.8,0) 2(0.8,0)
  silkscreen extent -1.52,-0.69 1.52,0.69, body extent -0.87,-0.47 0.87,0.47, height 1
0805_HV [mil] "0805 with 30mil clearance between pads"
  rect 50x63 smd: 1(-40,0) 2(40,0)
  silkscreen extent -74,-40 74,40, body extent -43,-29 43,29, height 57
1206 [mm] "1206 from SM-752 data"
  rect 1.3x1.85 smd: 1(-1.45,0) 2(1.45,0)
  silkscreen extent -2.4,-1.21 2.4,1.21, body extent -1.7,-0.9 1.7,0.9, height 1.35
1206_180 [mm] "1206_180"
  rect 1.1x1.6 smd: 1(-1.7,0) 2(1.7,0)
  silkscreen extent -0.9,-1 0.9,1, body extent -1.75,-0.95 1.75,0.95, height 1.8
1206L [mm] "1206 from SM-752 data"
  rect 1.1x1.75 smd: 1(-1.35,0) 2(1.35,0)
  silkscreen extent -0.4,-0.77 0.4,0.77, body extent -1.7,-0.9 1.7,0.9, height 1.35
1210_280 [mm] "SMD, 2-Leads, Body 3.6x2.8mm, Height 2.8mm"
  rect 1.1x2.2 smd: 1(-1.65,0) 2(1.65,0)
  silkscreen extent -0.84,-1.4 0.84,1.4, body extent -1.8,-1.4 1.8,1.4, height 2.8
3528-21 [mm] "Medium Density IPC, based on Kemet datasheet 2016-10-20"
  rrect6% 1.8x2.23 smd: 1(-1.46,0) 2(1.46,0)
  silkscreen extent -2.29,-1.5 0.76,1.5, body extent -1.85,-1.5 1.85,1.5, height 2.12
AssemblyNote [mm] "Assembly Note"
AssemblyNoteLabel [mm] "Assembly Note for PCB Labels"
Beckhoff_ZS7002-0001 [mm] "EtherCAT P, 4 Pos, TH"
  rrect50% 1.5x1.5 hole 1: 1(1.24,-1.24)
  round 1.5 hole 1: 2(1.24,1.24) 3(-1.24,-1.24) 4(-1.24,1.24)
  round 1.7 hole 1.2: S1(3.64,1.24) S2(-3.64,1.24)
  silkscreen extent -7,-7 7,7, body extent -7,-7 7,7, height 26
Binder_09_3420_81_04 [mm] "M8 Socket, 4Pos, TH"
  rrect50% 1.8x1.8 hole 1.3 rot 18: 1(-1.7,0.5)
  round 1.8 hole 1.3: 2(-1.075,-1.45) 3(1.7,0.5) 4(1.075,-1.45)
  round 4.5 hole 3: S1(-6.25,0) S2(6.25,0)
  silkscreen extent -6.07,-6.4 6.07,6.8, body extent -6.4,-6.41 6.4,6.39, height 15.7
DDC0006A_N [mm]
  rrect17% 1x0.6 smd: 1(-1.375,0.95) 2(-1.375,0) 3(-1.375,-0.95) 4(1.375,-0.95) 5(1.375,0) 6(1.375,0.95)
  silkscreen extent -1.75,-1.52 0.7,1.53, body extent -1.43,-1.48 1.43,1.49, height 0.92
Diode_0603 [mm] "Based on Bourns recommended land pattern Rev 10/09"
  rect 0.7x1 smd: 1(-0.65,0) 2(0.65,0)
  silkscreen extent -1.5,-0.8 0.9,0.8, body extent -0.9,-0.5 0.9,0.5, height 0.85
DNK0008A [mm] "SON, 8-Leads, Body 5x6mm"
  rrect39% 0.86x0.51 smd paste-0.05 mask-0.05: 1(-2.82,1.905) 2(-2.82,0.635) 3(-2.82,-0.635) 4(-2.82,-1.905) 5(2.82,-1.905) 6(2.82,-0.635) 7(2.82,0.635) 8(2.82,1.905)
  rrect8% 1.48x1.27 on Top Paste: 9(-0.18,-1.47) 9(-0.18,0) 9(-0.18,1.47) 9(1.5,-1.47) 9(1.5,0) 9(1.5,1.47)
  rrect5% 4.34x4.6 smd paste-3 mask-0.05: 9(1.08,0)
  silkscreen extent -3.2,-2.7 3.2,2.7, body extent -3.05,-2.55 3.05,2.55, height 1.06
DRL0005A [mm] "SOTFL, 5-Flat Leads, Body 1.2x1.6x0.6mm, Pitch 0.5mm, TI recommended"
  rrect33% 0.67x0.3 smd: 1(-0.74,0.5) 2(-0.74,0) 3(-0.74,-0.5) 4(0.74,-0.5) 5(0.74,0.5)
  silkscreen extent -0.9,-0.95 0.5,0.95, body extent -0.85,-0.85 0.85,0.85, height 0.62
DRV0006A [mm] "SON, 6-Leads, Body 2x2mm, Pitch 0.65mm, Thermal Pad 1.6x1mm, TI Recommended"
  rrect33% 0.45x0.3 smd: 1(-0.975,0.65) 2(-0.975,0) 3(-0.975,-0.65) 4(0.975,-0.65) 5(0.975,0) 6(0.975,0.65)
  rrect14% 1x0.7 on Top Paste: 7(0,0.45) 7(0,-0.45)
  rrect10% 1x1.6 smd paste-0.5: 7(0,0)
  silkscreen extent -1.05,-1.2 1.05,1.2, body extent -1.05,-1.05 1.05,1.05, height 0.81
FCC_disclaimer [mm]
Fiducial10-20 [mm]
  round 1 smd mask+0.5: 1(0,0)
  Top Layer keep-out circle w1.178: c0,0 r0.5
Keystone5001 [mil] "For Keystone 500x miniature loop terminals"
  round 80 hole 40: 1(0,0)
  silkscreen extent -52,-52 52,52, body extent -49,-49 49,49, height 182
Keystone5004 [mil] "For Keystone 500x miniature loop terminals"
  round 80 hole 40: 1(0,0)
  silkscreen extent -52,-52 52,52, body extent -49,-49 49,49, height 182
KRL1220 [mm] "Susumu"
  rect 0.75x1.5 smd: 1(-1.125,0) 2(1.125,0)
  silkscreen extent -0.5,-0.85 0.5,0.85, body extent -1.1,-0.72 1.1,0.72, height 0.7
Label_650x200 [mil] "Thermal Transfer Label"
  round 1 on Mech13: 0(0,0)
  silkscreen extent -325,-100 325,100, body extent -325,-100 325,100, height 1
Molex_039544-3002 [mm] "Terminal Block, 5.08mm, 2x1, TH"
  rect 2.15x2.15 hole 1.65: 1(-2.54,0)
  round 2.15 hole 1.65: 2(2.54,0)
  silkscreen extent -5.5,-4.8 5.08,5.11, body extent -5.08,-4.8 5.08,5.11, height 14.48
Molex_0022284023 [mm] "Header, 2.54mm, 2x1, TH"
  rect 1.55x1.55 hole 1.02: 1(-1.27,0)
  round 1.55 hole 1.02: 2(1.27,0)
  silkscreen extent -2.54,-1.24 2.54,1.5, body extent -2.54,-1.24 2.54,1.24, height 8.4
MTGP_4-40_PanHead [mm] "4-40 Mounting Hole, Plated, for Pan Head"
  round 6.4 hole 3.5: 1(0,0)
MUB10A_N [mm] "TSSOP, 10-Leads, Body 3x3mm, Pitch 0.5mm, IPC Medium Density"
  oval 1.7x0.3 smd: 1(-2.05,1) 2(-2.05,0.5) 3(-2.05,0) 4(-2.05,-0.5) 5(-2.05,-1) 6(2.05,-1) 7(2.05,-0.5) 8(2.05,0) 9(2.05,0.5) 10(2.05,1)
  silkscreen extent -2.17,-1.6 0.8,1.82, body extent -1.6,-1.6 1.6,1.6, height 1.09
Net-Tie_10mil [mil] "10mil net tie, no solder mask opening, no solder paste"
  rect 10x10 smd paste-5 mask-5: 1(-10,0) 2(10,0)
  Top Layer region: -6,5 6,5 6,-5 -6,-5
Pb-Free_Overlay_Small [mm]
  silkscreen extent -1.16,-1.17 1.17,1.17
RKG0041A [mm] "QFN-41, 9X11mm"
  round 0.6 smd: 1(-4.1,5.05)
  rect 0.95x0.6 smd paste-0.025: 2(-4.425,3.6) 3(-4.425,2.7) 4(-4.425,1.8) 5(-4.425,0.9) 6(-4.425,0) 7(-4.425,-0.9) 8(-4.425,-1.8) 9(-4.425,-2.7) 10(-4.425,-3.6) 20(4.425,-3.6) 21(4.425,-2.7) 22(4.425,-1.8) 23(4.425,-0.9) 24(4.425,0) 25(4.425,0.9) 26(4.425,1.8) 27(4.425,2.7) 28(4.425,3.6)
  rect 1.6x1.7 smd paste-0.8: 11(-4.1,-5.05) 19(4.1,-5.05) 29(4.1,5.05)
  rect 0.6x0.95 smd paste-0.025: 12(-2.7,-5.425) 13(-1.8,-5.425) 14(-0.9,-5.425) 15(0,-5.425) 16(0.9,-5.425) 17(1.8,-5.425) 18(2.7,-5.425) 30(2.7,5.425) 31(1.8,5.425) 32(0.9,5.425) 33(0,5.425) 34(-0.9,5.425) 35(-1.8,5.425) 36(-2.7,5.425)
  rect 2.3x2.25 smd paste-1.2 mask-1.15: 37(-0.22,3.3)
  rect 3.1x2.2 smd paste-1.1: 38(-1.3,-0.11) 39(-1.3,-3.59)
  rect 1.4x1.24 smd paste-0.7: 40(2.33,-4.06)
  rect 2.04x3.05 smd paste-1.02: 41(2.65,-1.32)
  Top Layer region: -4.9,5.9 -4.9,4.2 -3.913,4.2 -3.3,4.815 -3.3,5.9 -4.9,5.9
  silkscreen extent -5.13,-6.11 5.12,6.12, body extent -4.57,-5.57 4.57,5.57, height 2.91
SMC [mil] "Molded Diode, 2-Leads, Body 6.9x5.8mm, IPC Medium Density, based on OnSemi component dimensions and land patterns"
  rect 110x150 smd: 1(-140.49,0) 2(140.49,0)
  silkscreen extent -221,-124 189,123, body extent -156,-116 156,116, height 91
SOD-123 [mm] "On Semi recommended land pattern"
  rect 0.915x1.22 smd: 1(-1.637,0) 2(1.637,0)
  silkscreen extent -2.74,-1.17 2.03,1.17, body extent -1.93,-0.9 1.93,0.9, height 1.35
WE-LHMI_7030 [mm] "Wurth"
  rect 2.95x3.5 smd: 1(-2.725,0) 2(2.725,0)
  silkscreen extent -3.55,-3.55 3.55,3.55, body extent -3.8,-3.45 3.8,3.45, height 3
WL-SMCW_Blue [mm] "SMD, 2-Leads, Body 1.6x0.8mm"
  rect 0.8x0.8 smd: 1(-0.8,0) 2(0.8,0)
  silkscreen extent -1.9,-0.8 1.2,0.8, body extent -0.85,-0.45 0.85,0.45, height 0.8
WL-SMCW_GREEN [mm] "WURTH"
  rect 0.8x0.8 smd: 1(-0.8,0) 2(0.8,0)
  silkscreen extent -1.9,-0.8 1.2,0.8, body extent -0.85,-0.45 0.85,0.45, height 0.8
WL-SMCW_RED [mm] "WURTH"
  rect 0.8x0.8 smd: 1(-0.8,0) 2(0.8,0)
  silkscreen extent -1.9,-0.8 1.2,0.8, body extent -0.85,-0.45 0.85,0.45, height 0.8
Wurth_60900213421 [mil] "Shunt, 2.54mm, Black"
  round 1 on Mech3: 0(0,0)
  body extent -98,-48 98,48, height 236
Wurth_61300621121 [mm] "Header, 2.54mm, 3x2, TH"
  rect 1.6x1.6 hole 1.1: 1(-1.27,2.54)
  round 1.6 hole 1.1: 2(1.27,2.54) 3(-1.27,0) 4(1.27,0) 5(-1.27,-2.54) 6(1.27,-2.54)
  silkscreen extent -2.8,-3.82 2.54,3.8, body extent -2.54,-3.82 2.54,3.8, height 7.27

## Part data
C1 C12 C15_Up C15_Us C16_Up C16_Us: "CAP, CERM, 0.1 µF, 100 V,+/- 10%, X7R, 1206", Cap_Case=1206, Manufacturer=MuRata, Supplier Part Number 1=490-3364-1-ND, TempCo=X7R, Tolerance_%=10, Value1=Unknown, Value2=100V, ValueDisplayed=0.1µF
C2 C10: "CAP, Tantalum Polymer, 10 µF, 35 V,+/- 20%, 0.2 ohm, 3528-21 SMD", Cap_Case=3528-21, Manufacturer=AVX, Supplier Part Number 1=478-9409-1-ND, Tolerance_%=20, Value1="0.2 ohm", Value2=35V, ValueDisplayed=10µF
C3 C4 C6 C7 C14_Up C14_Us C17_Up C17_Us C24: "CAP, CERM, 1 µF, 100 V,+/- 10%, X7R, 1206", Cap_Case=1206, Manufacturer=MuRata, Supplier Part Number 1=490-3909-1-ND, TempCo=X7R, Tolerance_%=10, Value1=Unknown, Value2=100V, ValueDisplayed=1µF
C5 C8 C9 C11: "CAP, CERM, 0.01 µF, 500 V,+/- 10%, X7R, 1206", Cap_Case=1206, Manufacturer=Vishay-Vitramon, Supplier Part Number 1=720-1021-1-ND, TempCo=X7R, Tolerance_%=10, Value2=500V, ValueDisplayed=0.01µF
C13_Up C13_Us C18_Up C18_Us C23 C25 C28: "CAP, CERM, 4.7 µF, 50 V,+/- 10%, X7R, 1206", Cap_Case=1206, Manufacturer=MuRata, Supplier Part Number 1=24R6347, TempCo=X7R, Tolerance_%=10, Value1=Unknown, Value2=50V, ValueDisplayed=4.7µF
C19_Up C19_Us: "CAP, CERM, 0.1 µF, 100 V,+/- 10%, X7R, 0603", Cap_Case=0603, Manufacturer=MuRata, Supplier Part Number 1=490-3285-1-ND, TempCo=X7R, Tolerance_%=10, Value1=Unknown, Value2=100V, ValueDisplayed=0.1µF
C20_Up C20_Us: "CAP, CERM, 1000 pF, 50 V,+/- 10%, X5R, 0603", Cap_Case=0603, Manufacturer=MuRata, Supplier Part Number 1=GRM188R61H102KA01D-ND, TempCo=X5R, Tolerance_%=10, Value2=50V, ValueDisplayed=1000pF
C21_Up C21_Us: "CAP, CERM, 3.3 µF, 16 V,+/- 10%, X7R, 0805", Cap_Case=0805, Manufacturer=MuRata, Supplier Part Number 1=GRM21BR71C335KA99L-ND, TempCo=X7R, Tolerance_%=10, Value2=16V, ValueDisplayed=3.3µF
C22_Up C22_Us: "CAP, CERM, 0.1 µF, 50 V,+/- 10%, X7R, 0603", Cap_Case=0603, Manufacturer=AVX, Supplier Part Number 1=478-5052-1-ND, TempCo=X7R, Tolerance_%=10, Value1=Unknown, Value2=50V, ValueDisplayed=0.1µF
C26 C29 C30: "CAP, CERM, 22 µF, 25 V,+/- 20%, X5R, 1210", Cap_Case=1210, Manufacturer=AVX, Supplier Part Number 1=96M1536, TempCo=X5R, Tolerance_%=20, Value2=25V, ValueDisplayed=22µF
C27: "CAP, CERM, 0.022 µF, 50 V,+/- 10%, X7R, 0603", Cap_Case=0603, Manufacturer=MuRata, Supplier Part Number 1=490-1517-1-ND, TempCo=X7R, Tolerance_%=10, Value1=Unknown, Value2=50V, ValueDisplayed=0.022µF
D1 D6: "Diode, TVS, Bi, 33 V, SMC", Manufacturer=Bourns, Power_W=5, Supplier Part Number 1=SMCJ33CABCT-ND, Value1=5W
D2 D4 D11: "LED, Green, SMD", Color=Green, Manufacturer="Wurth Elektronik", Supplier Part Number 1=732-4971-1-ND, Value1=W, Value2=3.2V
D3 D5: "LED, Red, SMD", Color=Red, Manufacturer="Wurth Elektronik", Power_TotalModule=0.072, Supplier Part Number 1=732-4978-1-ND, Value1=0.072W, Value2=2V
D7_Up D7_Us D9_Up D9_Us: "Diode, Switching, 100 V, 0.15 A, 0603 Diode", Manufacturer=Bourns, Supplier Part Number 1=652-CD0603-S01575, Value1=0.15A, Value2=1V
D8_Up D8_Us: "LED, Blue, SMD", Color=Blue, Manufacturer="Wurth Elektronik", Power_TotalModule=0.105, Supplier Part Number 1=732-4966-1-ND, Value1=0.105W, Value2=3.2V
D10_Up D10_Us: "Diode, Zener, 33 V, 500 mW, SOD-123", Manufacturer="Diodes Inc.", Power_W=0.5, Supplier Part Number 1=BZT52C33-FDICT-ND, Value1=0.5W
FID1 FID2 FID3: "Fiducial mark.  There is nothing to buy or mount.", Manufacturer=N/A
J1 J6 J7: "Terminal Block, 5.08mm, 2x1, TH", Color=Black, Current_A=15, Manufacturer=Molex, Supplier Part Number 1=WM7853-ND, Voltage_V=300
J2 J3 J8 J9: "Header, 2.54mm, 3x2, Gold, TH", Color=Black, Manufacturer="Wurth Elektronik", Supplier Part Number 1=732-5295-ND
J4: "M8 Socket, 4Pos, Gold, TH", Current_A=4, Manufacturer=Binder-Connector, Voltage_V=60
J5: "EtherCAT P, 4 Pos, TH", Current_A=3, Manufacturer=Beckhoff, Voltage_V=30
J10_Up J10_Us J11: "Header, 2.54mm, 2x1, Tin, TH", Color=Black, Current_A=4, Manufacturer=Molex, Supplier Part Number 1=WM50016-02-ND, Voltage_V=250
L1 L2 L3 L4: "Inductor, Shielded Drum Core, Powdered Iron, 6.8 µH, 3.4 A, 0.054 ohm, SMD", Manufacturer="Wurth Elektronik", Supplier Part Number 1=732-3377-1-ND, Value1="0.054 ohm", Value2=3.4A, ValueDisplayed=6.8µH
LBL1: library part THT-14-423-10, "Thermal Transfer Printable Labels, 0.650\" W x 0.200\" H - 10,000 per roll", Alternate Manufacturer=-, Manufacturer=Brady, Supplier Part Number 1=2065596
Logo1: library part Pb-Free
Logo2: library part FCC_disclaimer, "FCC_disclaimer"
MH1: library part "Mounting Hole (Imperial) with Pads", "PCB Mounting Hole", Manufacturer=Any, PartNumber=N/A
NT1: "Single point connection between nets."
Q1_Up Q1_Us Q2_Up Q2_Us: "MOSFET, N-CH, 60 V, 100 A, DNK0008A (VSON-CLIP-8)", Alternate Manufacturer=None, Manufacturer="Texas Instruments", Supplier Part Number 1=296-41076-1-ND, Value1="0.0033 ohm", Value2="41 nC"
R1 R6 R10_Up R10_Us: "RES, 10.0 k, 1%, 0.1 W, 0603", Manufacturer=Vishay-Dale, Power_W=0.1, Supplier Part Number 1=541-10.0KHCT-ND, TempCo="100 ppm/C", Tolerance_%=1, Value1=1%, Value2=0.1W, Value_Code=10k0, ValueDisplayed=10.0k
R2 R3 R4 R5: "RES, 1.00 M, 1%, 0.25 W, 1206", Manufacturer=Vishay-Dale, Power_W=0.25, Supplier Part Number 1=541-1.00MFCT-ND, TempCo="100 ppm/C", Tolerance_%=1, Value1=1%, Value2=0.25W, Value_Code=1M00, ValueDisplayed=1.00M
R7_Up R7_Us R8_Up R8_Us: "RES, 0.018, 1%, 0.5 W, AEC-Q200 Grade 0, 0805", Manufacturer="Susumu Co Ltd", Power_W=0.5, Supplier Part Number 1=408-1547-1-ND, TempCo="50 ppm/C", Tolerance_%=1, Value1=1%, Value2=0.5W, Value_Code=R018, ValueDisplayed=0.018
R9_Up R9_Us: "RES, 100, 1%, 0.1 W, 0603", Manufacturer="Yageo America", Power_W=0.1, Supplier Part Number 1=311-100HRCT-ND, TempCo="200 ppm/C", Tolerance_%=1, Value1=1%, Value2=0.1W, Value_Code=100R, ValueDisplayed=100
R11_Up R11_Us R12_Up R12_Us: "RES, 47.0 k, 1%, 0.1 W, 0603", Manufacturer="Yageo America", Power_W=0.1, Supplier Part Number 1=311-47.0KHRCT-ND, TempCo="200 ppm/C", Tolerance_%=1, Value1=1%, Value2=0.1W, Value_Code=47k0, ValueDisplayed=47.0k
R13_Up R13_Us: "RES, 115 k, 1%, 0.1 W, 0603", Manufacturer="Yageo America", Power_W=0.1, Supplier Part Number 1=311-115KHRCT-ND, TempCo="200 ppm/C", Tolerance_%=1, Value1=1%, Value2=0.1W, Value_Code=115k
R14_Up R14_Us: "RES, 6.20 k, 1%, 0.1 W, 0603", Manufacturer="Yageo America", Power_W=0.1, Supplier Part Number 1=311-6.20KHRCT-ND, TempCo="200 ppm/C", Tolerance_%=1, Value1=1%, Value2=0.1W, Value_Code=6k20, ValueDisplayed=6.20k
R15_Up R15_Us: "RES, 4.42 k, 1%, 0.1 W, 0603", Manufacturer="Yageo America", Power_W=0.1, Supplier Part Number 1=311-4.42KHRCT-ND, TempCo="200 ppm/C", Tolerance_%=1, Value1=1%, Value2=0.1W, Value_Code=4k42, ValueDisplayed=4.42k
R16_Up R16_Us: "RES, 14.0 k, 1%, 0.1 W, 0603", Manufacturer=Vishay-Dale, Power_W=0.1, Supplier Part Number 1=541-14.0KHCT-ND, TempCo="100 ppm/C", Tolerance_%=1, Value1=1%, Value2=0.1W, Value_Code=14k0, ValueDisplayed=14.0k
R17: "RES, 174 k, 1%, 0.1 W, 0603", Manufacturer=Vishay-Dale, Power_W=0.1, Supplier Part Number 1=541-174KHCT-ND, TempCo="100 ppm/C", Tolerance_%=1, Value1=1%, Value2=0.1W, Value_Code=174k
R18: "RES, 140 k, 1%, 0.1 W, 0603", Manufacturer=Vishay-Dale, Power_W=0.1, Supplier Part Number 1=541-140KHCT-ND, TempCo="100 ppm/C", Tolerance_%=1, Value1=1%, Value2=0.1W, Value_Code=140k
R19: "RES, 84.5 k, 1%, 0.1 W, 0603", Manufacturer=Vishay-Dale, Power_W=0.1, Supplier Part Number 1=541-84.5KHCT-ND, TempCo="100 ppm/C", Tolerance_%=1, Value1=1%, Value2=0.1W, Value_Code=84k5, ValueDisplayed=84.5k
R20: "RES, 2.21 k, 1%, 0.1 W, 0603", Manufacturer=Vishay-Dale, Power_W=0.1, Supplier Part Number 1=541-2.21KHCT-ND, TempCo="100 ppm/C", Tolerance_%=1, Value1=1%, Value2=0.1W, Value_Code=2k21, ValueDisplayed=2.21k
R21: "RES, 11.5 k, 1%, 0.1 W, 0603", Manufacturer=Vishay-Dale, Power_W=0.1, Supplier Part Number 1=541-11.5KHCT-ND, TempCo="100 ppm/C", Tolerance_%=1, Value1=1%, Value2=0.1W, Value_Code=11k5, ValueDisplayed=11.5k
R22: "RES, 267 k, 1%, 0.1 W, 0603", Manufacturer=Vishay-Dale, Power_W=0.1, Supplier Part Number 1=541-267KHCT-ND, TempCo="100 ppm/C", Tolerance_%=1, Value1=1%, Value2=0.1W, Value_Code=267k
SH-J1 SH-J2 SH-J3 SH-J4 SH-J5 SH-J6 SH-J7 SH-J8 SH-J9_Up SH-J9_Us SH-J10: "Shunt, 2.54mm, Gold, Black", Manufacturer="Wurth Elektronik", Supplier Part Number 1=732-2678-ND
TP1 TP2 TP3 TP4 TP5: "Test Point, Miniature, Black, TH", Color=Black, Manufacturer=Keystone, Supplier Part Number 1=36-5001-ND
TP6_Up TP6_Us TP7_Up TP7_Us: "Test Point, Miniature, Yellow, TH", Color=Yellow, Manufacturer=Keystone, Supplier Part Number 1=36-5004-ND
U1 U2: "Dual-Channel High-Speed ESD Protection, DRL0005A (SOT-OTHER-5)", Alternate Manufacturer="Texas Instruments"
U3_Up U3_Us: "High Side OR-ing FET Controller, DDC0006A (SOT-23-T-6)", Alternate Manufacturer="Texas Instruments"
U4_Up U4_Us: "Positive High Voltage Hot Swap / Inrush Current Controller with Power Limiting, 10-pin MSOP, Pb-Free", Manufacturer="Texas Instruments", PackageTopMarking=ZXTT*SNBB, PowerWise=N, Supplier Part Number 1=LM5069MM-2TR-ND
U5: "SIMPLE SWITCHER(R) 7V to 50V, 2.5A Wide Vin Power Module in Small Package, RKG0041A (B1QFN-41)", Alternate Manufacturer="Texas Instruments", Alternate PartNumber=LMZ35003RKGT
U6_TVS3300_Up U6_TVS3300_Us U7_TVS3300_Up U7_TVS3300_Us: "33V Precision Surge Protection Clamp, DRV0006A (WSON-6)", Alternate Manufacturer="Texas Instruments", Alternate PartNumber=TVS3300DRVT
ZZ1: library part AssemblyNoteLabel, Alternate Manufacturer=-
ZZ2 ZZ3 ZZ4: library part AssemblyNote, Alternate Manufacturer=-

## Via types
v1: diameter 0.5, hole 0.2, Top Layer to Bottom Layer, 134 vias
v2: diameter 0.61, hole 0.305, Top Layer to Bottom Layer, 15 vias
v3: diameter 0.6, hole 0.3, Top Layer to Bottom Layer, 6 vias
v4: diameter 0.5, hole 0.3, Top Layer to Bottom Layer, tented both sides, 6 vias
v5: diameter 1, hole 0.5, Top Layer to Bottom Layer, 6 vias
v6: diameter 1, hole 0.7, Top Layer to Bottom Layer, 2 vias

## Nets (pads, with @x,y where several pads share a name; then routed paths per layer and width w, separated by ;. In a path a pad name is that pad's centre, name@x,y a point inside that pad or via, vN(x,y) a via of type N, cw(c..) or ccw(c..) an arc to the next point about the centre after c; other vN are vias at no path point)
AGND: C27.2 D11.1 NT1.1 R21.1 R22.1 U5.1 U5.4 U5.5 U5.29 U5.30 U5.32 U5.33 U5.34 U5.37 | length 28
  Top Layer w0.3: U5.29@27.775,22.825 27.775,21.175 R22.1@27.95,21
  Top Layer w0.5: R21.1@21.95,23.25 21.95,23.239 22.864,22.325 26.475,22.325 26.75,22.6 26.8,22.6 U5.29@27.4,23.2 ; U5.33@31.5,22.825 31.5,21.2 D11.1@31.7,21
  Top Layer w0.6: U5.29@26.75,22.4 26.75,20.5 27.25,20 39.95,20 40.95,21 40.95,22.3
  other v4: 30.86,24.17 32.58,24.17 30.86,24.95 32.58,24.95 30.86,25.73 32.58,25.73
Buck_In: C23.1 C24.2 C28.1 J8.1 J8.2 J9.1 J9.2 R17.2 U5.26 U6_TVS3300_Us.1 U6_TVS3300_Us.2 U6_TVS3300_Us.3 U6_TVS3300_Us.7@61.5,17.25 | length 64.8
  Top Layer w0.5: R17.2@21.95,24.75 21.95,26.5 C28.1@22,26.55 ; U5.26@27,26.3 25.9,26.3 25.9,26.55 U5.26@27.075,26.55
  Top Layer w1: C24.2@20,26.55 22,26.55 22.5,26.55 25,26.55 25.9,26.55
  Top Layer w1.5: C24.2@20,26.25 20,19.52 J8.1@21.98,17.54 J8.2@24.52,17.54 J9.1@64.48,17.54 J9.2@67.02,17.54
  other v1: 60.95,17.25 62.05,17.25
BUCK_OUT: C25.1 C26.1 C29.1 C30.1 J6.1 J11.2 R18.1 R20.2 U5.10 U5.11 U5.12 U5.13 U5.14 U5.15 U5.39 | length 65.3
  Top Layer w0.5: R20.2@36.3,21 39.8,21 40.2,21.4 40.2,23.05 39.75,23.5 39.75,27.52 J11.2@38.5,28.77
  Top Layer w1: J6.1@7.5,30.04 12.71,35.25 v2(12.71,35.2) 25,35.2 27,35.2
  Bottom Layer w0.5: v2(12.71,35.2) 37,35.2 37.05,35.25 38.5,33.8 J11.2@38.5,28.77
GND: C9.2 C10.2 C11.2 C12.2 C13_Us.2 C14_Us.2 C15_Us.2 C16_Us.2 C17_Us.2 C18_Us.2 C20_Us.2 C21_Us.2 C22_Us.2 C23.2 C24.1 C25.2 C26.2 C28.2 C29.2 C30.2 D6.1 D8_Us.1 D9_Us.1 D10_Us.2 J6.2 J7.2 J10_Us.1 L3.1 NT1.2 R4.1 R5.1 R6.2 R14_Us.1 R15_Us.1 R16_Us.1 TP1.1 TP2.1 TP3.1 U4_Us.5 U5.8 U5.9 U5.16 U5.17 U5.18 U5.19 U5.20 U5.40 U7_TVS3300_Us.1 U7_TVS3300_Us.2 U7_TVS3300_Us.3 U7_TVS3300_Us.7@61.5,14.75 | length 164.1
  Top Layer w0.3: R6.2@27.25,8.8 27.25,10.25 27.3,10.3 27.5,10.5 C13_Us.2@27.7,10.3 ; 30.25,9.25 30.25,10.25 C14_Us.2@30.2,10.3 30.25,10.35 30.25,11.5 ; 32.7,11.75 C15_Us.2@32.7,10.65 32.7,9.55 32.75,9.5 ; 42.45,5.7 R14_Us.1@42.45,6.45 42.65,6.25 R15_Us.1@43.95,6.25 ; J10_Us.1@42.97,4 43.22,4.25 D8_Us.1@45.65,4.25 C20_Us.2@45.65,6.25 ; 43.95,5.55 R15_Us.1@43.95,6.25 ; R15_Us.1@43.95,6.45 R15_Us.1@43.95,6.25 ; C20_Us.2@45.45,6.45 C20_Us.2@45.65,6.25 ; C22_Us.2@47.65,6.45 U4_Us.5@47.65,8 ; C22_Us.2@47.7,6.25 C20_Us.2@45.65,6.25 ; 52.2,3.12 C21_Us.2@52.2,3.984 ; 54.2,3.7 54.2,4.113 R16_Us.1@54.2,4.45 ; 56.5,3.5 D10_Us.2@56.5,4.113 56.5,5 ; R15_Us.1@43.95,6.25 C20_Us.2@45.65,6.25
  Top Layer w0.5: v1(4.5,37) C11.2@6.25,37 ; 4.75,7.96 J7.2@7.45,7.96 J7.2@7.5,7.96 ; 6,24.96 J6.2@7.5,24.96 ; v1(6.25,35.5) C11.2@6.25,37 ; C11.2@6.25,37.05 C11.2@6.25,37 ; 7.5,5.75 J7.2@7.5,7.96 ; 7.5,10 J7.2@7.5,7.96 ; 7.5,23.5 J6.2@7.5,24.96 ; 7.5,26.5 J6.2@7.5,24.96 ; v1(8.75,35.5) R5.1@8.75,37 ; R5.1@8.75,37.05 R5.1@8.75,37 ; v1(10.5,37) R5.1@8.75,37 ; v1(21.5,5.25) C12.2@21.5,6.55 ; 21.5,7.75 C12.2@21.5,6.55 ; 22.95,6.55 C12.2@21.5,6.55 ; J10_Us.1@42.97,4 J10_Us.1@42.97,4.25 ; C21_Us.2@52.2,3.984 52.329,4.113 54.2,4.113 v1(55.25,4.113) D10_Us.2@56.5,4.113 ; 59.75,14 59.75,13.775 U7_TVS3300_Us.1@60.85,13.775 U7_TVS3300_Us.2@61.5,13.775 62.05,13.775 v1(62.05,14.75) ; v1(59.75,14.25) 60,14 ; v1(60.75,6.75) R4.1@62.05,6.75 ; 62.05,3.125 C9.2@62.05,4.25 ; C11.2@6.25,37 R5.1@8.75,37
  Top Layer w1: J6.2@7.5,24.96 9.96,24.96 15.5,30.5 ; C30.2@14.75,31.85 C25.2@24.95,31.85 ; D6.1@16.7,7.431 17.581,6.55 C12.2@21.5,6.55 ; C24.1@19.75,29.95 C23.2@24.75,29.95 ; 26.6,10.3 27.3,10.3 C13_Us.2@27.7,10.3 C14_Us.2@30.2,10.3 32.35,10.3 C15_Us.2@32.7,10.65 ; C16_Us.2@56.75,9.65 58.65,9.65 C17_Us.2@59.25,9.05 C18_Us.2@61.75,9.05 62.05,8.75 R4.1@62.05,6.75 C9.2@62.05,4.5 ; v1@60,14.25 61.75,14.25 ; 60,14.75 U7_TVS3300_Us.7@61.75,14.75 ; C10.2@78.96,12.75 C10.2@79.225,12.75
  Top Layer w1.5: J7.2@7.5,7.96 16.171,7.96 D6.1@16.7,7.431 ; C18_Us.2@61.75,9.05 62.45,9.75 77.55,9.75 78.96,11.16 C10.2@78.96,12.75 ; C10.2@79.225,12.75 L3.1@84.725,18.25
  Bottom Layer w0.4: 5.75,8 J7.2@7.41,8 ; 7.45,9.7 J7.2@7.45,8 ; 7.5,6 J7.2@7.5,7.91 ; 7.5,9.75 J7.2@7.5,8 ; 7.5,23.25 J6.2@7.5,24.96 ; 7.5,26.75 J6.2@7.5,24.96 ; 9.21,8 J7.2@7.5,8 ; 9.25,24.96 J6.2@7.5,24.96 ; J7.2@7.41,8 J7.2@7.45,7.96 ; J7.2@7.41,8 J7.2@7.45,8 ; J7.2@7.45,7.96 J7.2@7.5,7.91 ; J7.2@7.45,7.96 J7.2@7.45,8 ; J7.2@7.45,8 J7.2@7.5,8 ; J7.2@7.5,7.91 J7.2@7.5,8 ; J6.2@7.5,24.96 7.46,25 5.75,25 5.79,24.96 J6.2@7.5,24.96
  other v1: 53.75,3 45.5,3.25 60.75,4.25 16.75,5.5 60.75,5.5 60.75,8 29,8.75 56.75,8.75 31.75,9 40.75,10 49.75,10 60.95,14.75 33,19 11.25,19.25 18.5,19.25 23.25,19.25 42.5,19.25 51.5,19.25 61.5,19.25 11.25,21 11.25,22.75 26,29.75 15,30 16.5,30 17.75,30 30.6,30.1 31.3,30.1 32,30.1 32.7,30.1 33.4,30.1 34.1,30.1 34.8,30.1 26,30.5 26,31.25 28,31.9 26,32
